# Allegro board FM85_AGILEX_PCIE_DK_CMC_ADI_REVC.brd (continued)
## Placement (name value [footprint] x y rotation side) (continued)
R383  20.0K  [0402]  7.32 34.02 90 top
R384  10.0K  [0402]  40.49 16.97 90 top
R385  22.0  [0402]  34.83 15.01 0 top
R391  10  [0402]  36.32 30.2 45 bottom
R401  DNI  [0402]  25.03 35.26 0 top
R408  1K  [0402]  26.35 50.52 270 bottom
R409  1K  [0402]  26.35 49.74 270 bottom
R412  1K  [0402]  28.1 49.74 270 bottom
R413  10.0K  [0402]  26.37 48.95 90 bottom
R414  DNI  [0402]  244.48 31.07 90 bottom
R415  10.0K  [0402]  244.86 32.51 0 bottom
R416  10.0K  [0402]  244.02 32.51 0 bottom
R423  10.0K  [0402]  27.77 34.37 0 bottom
R429  1K  [0402]  230.51 106 180 bottom
R430  1K  [0402]  229.37 105.97 180 bottom
R431  1K  [0402]  233.05 106 180 bottom
R434  1K  [0402]  225.15 105.97 180 bottom
R435  10.0K  [0402]  54.24 12.52 270 bottom
R436  DNI  [0402]  41.16 61.17 180 bottom
R437  DNI  [0402]  40.14 61.17 180 bottom
R438  0,DNI  [0402]  39.12 61.17 180 bottom
R439  DNI  [0402]  38.11 61.17 180 bottom
R440  33.2  [0402]  51.32 13.16 270 bottom
R441  DNI  [0402]  37.09 61.17 180 bottom
R442  DNI  [0402]  35.06 61.17 180 bottom
R443  33.2  [0402]  51.32 14.3 270 bottom
R444  4.7K  [0402]  42.17 61.17 180 bottom
R445  10.0K  [0402]  49.16 11 180 bottom
R446  33.2  [0402]  47.25 13.92 180 bottom
R447  33.2  [0402]  48.52 13.92 180 bottom
R448  4.7K  [0402]  244.1 50.37 270 bottom
R449  4.7K  [0402]  244.1 51.39 270 bottom
R450  4.7K  [0402]  244.1 52.4 270 bottom
R451  10.0K  [0402]  46.62 11 0 bottom
R452  4.7K  [0402]  244.1 54.43 270 bottom
R453  10.0K  [0402]  74.64 78.34 180 bottom
R454  0  [0402]  68.42 81.77 270 top
R455  0  [0402]  68.42 80.75 270 top
R456  0  [0402]  68.42 79.73 270 top
R457  4.7K  [0402]  251.85 57.23 180 bottom
R458  0  [0402]  68.42 78.72 270 top
R459  0  [0402]  72.69 77.45 180 bottom
R460  0  [0402]  76.17 78.72 90 bottom
R461  0  [0402]  73.58 77.45 180 bottom
R462  10.0K  [0402]  29.47 52.4 180 bottom
R463  10.0K  [0402]  31.5 52.4 180 bottom
R464  10.0K  [0402]  34.55 52.4 180 bottom
R465  10.0K  [0402]  174.02 92.03 270 bottom
R466  10.0K  [0402]  32.27 62.69 0 bottom
R467  10.0K DNI  [0402]  30.49 52.4 0 bottom
R468  10.0K DNI  [0402]  32.52 52.4 0 bottom
R469  10.0K DNI  [0402]  33.54 52.4 0 bottom
R470  0  [0402]  166.02 89.87 90 bottom
R471  0  [0402]  166.02 90.88 90 bottom
R472  0  [0402]  166.02 91.8 90 bottom
R473  0  [0402]  166.05 92.76 90 bottom
R474  DNI  [0402]  169.96 95.46 0 bottom
R475  DNI  [0402]  170.97 95.46 0 bottom
R476  750  [0402]  174.02 91.01 270 bottom
R477  200K  [0402]  245.29 92.15 270 bottom
R478  DNI  [0402]  242.2 79.2 180 bottom
R479  5.49M  [0402]  240.29 73.36 270 bottom
R480  4.7K  [0402]  240.42 79.2 0 bottom
R481  10.0K  [0402]  241.31 79.2 180 bottom
R482  0  [0402]  243.09 79.2 0 bottom
R483  10  [0402]  217.05 85.93 180 top
R484  100K  [0402]  241.18 72.34 90 bottom
R485  100K  [0402]  212.61 86.57 180 bottom
R486  200K  [0402]  242.07 73.36 270 bottom
R487  41.2K  [0402]  217.18 88.6 270 bottom
R488  5.76K  [0402]  217.18 89.49 90 bottom
R489  240  [0402]  217.18 91.26 270 bottom
R490  1K  [0402]  214 85.8 0 bottom
R491  DNI  [0402]  211.21 86.57 90 bottom
R492  5.49M  [0402]  214.76 82.12 0 bottom
R493  4.7K  [0402]  211.93 80.6 270 bottom
R494  10.0K  [0402]  211.59 84.79 180 top
R495  0  [0402]  211.21 87.58 270 bottom
R496  100K  [0402]  214.76 83.9 180 bottom
R497  200K  [0402]  214.89 85.8 0 bottom
R498  10.0K  [0402]  241.94 73.1 0 top
R499  10.0K  [0402]  238.89 73.1 0 top
R500  200K  [0402]  240.67 79.58 0 top
R501  60.4K  [0402]  244.74 79.2 0 bottom
R502  1.91K  [0402]  240.16 78.18 90 top
R503  60.4K  [0402]  243.72 70.06 180 bottom
R504  20.0K  [0402]  243.72 71.96 0 bottom
R505  6.04K  [0402]  239.66 79.58 180 top
R546  0  [0402]  227.97 20.86 180 bottom
R547  0  [0402]  229.11 20.86 180 bottom
R578  100K  [0402]  232.52 59.95 180 bottom
R579  200K  [0402]  232.54 61.76 0 bottom
R580  10  [0402]  233.15 66.12 180 bottom
R581  DNI  [0402]  229.37 59.72 90 bottom
R582  100K  [0402]  231.22 59.95 180 bottom
R583  100K  [0402]  231.91 64.82 90 bottom
R584  DNI  [0402]  229.47 63.86 90 bottom
R585  DNI  [0402]  232.54 63.58 180 bottom
R586  DNI  [0402]  232.93 57.71 270 top
R587  100K  [0402]  229.47 62.59 90 bottom
R588  0  [0402]  231.38 63.41 0 bottom
R589  24.9K  [0402]  231.15 62 270 bottom
R590  8.25K  [0402]  231.16 58.85 90 top
R621  0  [0402]  236.64 20.27 0 top
R622  0  [0402]  239.88 20.26 0 top
R656  10K  [0402]  42.32 102.77 270 bottom
R657  35.7K  [0402]  43.47 105.82 0 top
R658  332K  [0402]  38.39 105.82 180 top
R659  14K  [0402]  43.72 104.04 180 top
R660  10K,DNI  [0402]  37.12 105.18 270 bottom
R661  14K  [0402]  42.7 104.04 180 top
R662  10K  [0402]  36.46 104.14 90 bottom
R663  1.0  [0402]  34.83 102.52 270 top
R664  10K,DNI  [0402]  37.37 105.82 180 top
R665  0  [0402]  95.26 82.25 0 bottom
R666  0  [0402]  96.27 82.25 0 bottom
R667  10K,DNI  [0402]  36.46 105.82 0 top
R668  10K  [0402]  208.44 36.17 0 bottom
R669  35.7K  [0402]  210.7 33.73 270 top
R670  332K  [0402]  209.43 37.16 90 top
R671  10K,DNI  [0402]  209.3 38.05 180 bottom
R672  10K  [0402]  208.41 38.05 0 bottom
R673  1.0  [0402]  206.13 39.45 180 top
R674  14K  [0402]  207.65 30.64 90 top
R675  14K  [0402]  207.63 31.57 90 top
R676  10K,DNI  [0402]  209.43 38.05 90 top
R677  0  [0402]  101.12 36.45 180 bottom
R678  0  [0402]  102.01 36.45 180 bottom
R679  10K,DNI  [0402]  209.43 38.94 270 top
R768  825E  [0402]  177.48 38.67 90 bottom
R815  10.0K  [0402]  47.42 28.63 0 top
R816  10.0K,DNI  [0402]  46.45 27.64 0 top
R817  0  [0402]  48.19 24.59 180 bottom
R818  10.0K  [0402]  46.45 25.38 180 top
R819  10.0K  [0402]  40.66 28.53 180 bottom
R820  10.0K  [0402]  39.76 30.03 90 bottom
R821  10.0K  [0402]  23.79 109.39 90 top
R822  10.0K, DNI  [0402]  25.83 109.54 90 top
R823  0  [0402]  25.83 108.65 270 top
R824  10.0K  [0402]  27.79 109 270 top
R825  10.0K  [0402]  20.75 107.89 180 top
R826  10.0K  [0402]  22.56 107.89 180 top
R835  DNI  [1206]  41.16 83.52 270 bottom
R836  0  [0402]  35.06 84.91 0 bottom
R837  4.7K  [0402]  35.06 82.88 180 bottom
R838  DNI  [0402]  31.5 81.87 90 bottom
R839  0  [0402]  31.5 80.98 90 bottom
R840  4.7K  [0402]  31.5 80.09 270 bottom
R853  0,DNI  [RESC1005X40L20L]  178.58 55.01 180 top
R854  1K  [0402]  244.1 49.35 90 bottom
R856  10.0K  [0402]  105.54 69.7 60 bottom
R857  0  [0402]  14.61 59.64 90 bottom
R858  0  [0402]  44.76 31.98 180 top
R859  0  [0402]  45.55 31.98 180 top
R865  0  [0402]  86.27 74.34 90 bottom
R866  1K  [0402]  105.55 70.7 60 bottom
R867  1K  [0402]  103.98 66.97 240 bottom
R868  36  [0402]  71.04 18.43 90 bottom
R869  36  [0402]  73.34 18.53 270 bottom
R870  36  [0402]  71.04 17.61 90 bottom
R871  36  [0402]  73.34 19.33 270 bottom
R872  36  [0402]  71.04 19.25 90 bottom
R873  36  [0402]  77.72 18.41 90 bottom
R874  36  [0402]  67.49 18.48 270 bottom
R875  36  [0402]  75.62 15.69 0 bottom
R876  36  [0402]  67.49 16 270 bottom
R877  36  [0402]  73.79 15.69 0 bottom
R878  36  [0402]  71.04 20.07 90 bottom
R879  36  [0402]  69.53 15.95 0 bottom
R880  36  [0402]  73.34 20.13 270 bottom
R881  36  [0402]  74.68 15.69 0 bottom
R882  36  [0402]  67.49 21.78 270 bottom
R883  36  [0402]  76.83 22.79 90 bottom
R884  36  [0402]  76.83 23.66 90 bottom
R885  36  [0402]  67.49 20.95 270 bottom
R886  36  [0402]  76.83 21.91 90 bottom
R887  36  [0402]  67.49 19.31 270 bottom
R888  36  [0402]  77.06 21 90 bottom
R889  36  [0402]  73.34 20.93 270 bottom
R890  36  [0402]  71.04 21.73 90 bottom
R891  36  [0402]  71.04 20.9 90 bottom
R892  36  [0402]  165.34 18.36 270 bottom
R893  36  [0402]  168.07 18.37 90 bottom
R894  36  [0402]  165.34 17.54 270 bottom
R895  36  [0402]  168.07 19.19 90 bottom
R896  36  [0402]  165.34 19.19 270 bottom
R897  36  [0402]  172.23 18.34 90 bottom
R898  36  [0402]  162.01 18.41 270 bottom
R899  36  [0402]  170.14 15.62 0 bottom
R900  36  [0402]  163.48 15.22 0 bottom
R901  36  [0402]  167.09 16.26 0 bottom
R902  36  [0402]  165.34 20.01 270 bottom
R903  36  [0402]  164.47 15.83 0 bottom
R904  36  [0402]  168.07 20.01 90 bottom
R905  36  [0402]  169.2 15.62 0 bottom
R906  36  [0402]  162.01 21.71 270 bottom
R907  36  [0402]  171.85 22.8 90 bottom
R908  36  [0402]  171.34 23.59 90 bottom
R909  36  [0402]  162.01 20.88 270 bottom
R910  36  [0402]  171.85 21.92 90 bottom
R911  36  [0402]  162.01 19.24 270 bottom
R912  36  [0402]  172.08 21.02 90 bottom
R913  36  [0402]  168.07 20.84 90 bottom
R914  36  [0402]  165.34 21.67 270 bottom
R915  36  [0402]  165.34 20.84 270 bottom
R916  4.7K  [0402]  65.41 45.93 270 bottom
R917  0  [0402]  66.17 49.35 90 bottom
R918  0,DNI  [0402]  65.41 46.94 90 bottom
R920  100K  [0402]  65.41 48.08 90 bottom
R921  10.0K  [0402]  73.54 46.56 90 bottom
R923  100K  [0402]  73.54 49.86 270 bottom
R925  66.5K  [0402]  73.54 48.85 90 bottom
R926  0  [0402]  175.16 53.73 180 bottom
R927  10.0K  [0402]  140.6 34.49 90 bottom
R928  0  [0402]  63.94 38.38 270 top
R929  0  [0402]  63.94 37.37 270 top
R930  0  [0402]  64.65 40.54 270 top
R931  0  [0402]  64.65 39.53 270 top
R932  0  [0402]  204.86 61.17 270 bottom
R933  0  [0402]  204.86 60.15 270 bottom
R934  0  [0402]  204.83 63.88 270 bottom
R935  0  [0402]  204.83 63.07 270 bottom
R936  49.9  [0402]  100.79 54.21 240 bottom
R937  49.9  [0402]  100.81 51.73 302 bottom
R939  49.9  [0402]  131.87 56.39 60 bottom
R941  49.9  [0402]  131.86 58.8 123 bottom
R942  10K  [0402]  56.4 102.82 270 bottom
R943  20k  [0402]  57.54 105.87 180 top
R944  169K  [0402]  52.46 105.87 180 top
R945  10.0K  [0402]  57.79 104.09 180 top
R946  10K,DNI  [0402]  51.19 105.23 270 bottom
R947  16.5K  [0402]  56.78 104.09 0 top
R948  10K  [0402]  50.43 104.35 90 bottom
R949  1.0  [0402]  48.9 102.57 270 top
R950  10K,DNI  [0402]  51.44 105.87 180 top
R951  0  [0402]  111.06 84.14 0 bottom
R952  0  [0402]  112.07 84.14 0 bottom
R953  10K,DNI  [0402]  50.43 105.87 0 top
R955  100K  [0402]  199.07 53.72 0 bottom
R956  100K  [0402]  199.4 55.02 90 bottom
R957  DNI  [0402]  206.56 56.31 90 top
R958  0  [0402]  203.33 50.14 90 bottom
R959  DNI  [0402]  201.43 49.25 270 bottom
R960  DNI  [0402]  206.58 55.38 270 top
R961  10  [0402]  99.85 36.45 0 bottom
R963  10  [0402]  98.84 36.45 180 bottom
R964  75K  [0402]  201.4 51.42 180 bottom
R965  100K  [0402]  202.9 45.88 90 bottom
R966  100K  [0402]  200.31 46.18 0 top
R967  DNI  [0402]  207.84 48.11 180 top
R969  0  [0402]  205.24 41.61 90 bottom
R970  332K  [0402]  206.53 41.51 180 bottom
R971  DNI  [0402]  203.33 40.72 270 bottom
R972  DNI  [0402]  208.29 46.81 270 top
R973  10  [0402]  127.26 36.65 0 bottom
R975  10  [0402]  126.25 36.65 180 bottom
R976  75K  [0402]  200.39 42.6 90 bottom
R977  4.7K  [0402]  202.9 45.09 90 bottom
R978  332K  [0402]  206.08 49.74 180 bottom
R979  4.7K  [0402]  201 53.47 90 bottom
R980  DNI  [0402]  205.32 54.57 0 bottom
R981  DNI  [0402]  203.7 43.83 45 bottom
R982  0  [0402]  249.82 46.94 270 bottom
R983  1K  [0402]  52.59 35.51 270 top
R984  1K  [0402]  53.47 33.86 0 top
R985  49.9  [0402]  55.51 34.45 270 top
R986  49.9  [0402]  57.28 34.45 90 top
R987  49.9  [0402]  59.19 34.37 270 top
R988  49.9  [0402]  60.97 34.37 90 top
R993  49.9  [0402]  214.97 57.1 270 bottom
R994  DNI  [0402]  204.48 66.14 0 bottom
R995  1K  [0402]  203.46 66.14 0 bottom
R996  49.9  [0402]  213.06 57.1 90 bottom
R997  49.9  [0402]  211.08 57.36 270 bottom
R998  49.9  [0402]  209.18 57.36 90 bottom
R999  4.7K  [0402]  97.72 32.44 270 bottom
R1000  0  [0402]  57.94 12.4 270 bottom
R1001  10.0K, DNI  [0402]  59.93 13.97 270 bottom
R1034  240  [0402]  97.87 36.45 0 bottom
R1047  10.0K  [0402]  144.79 105.44 0 bottom
R1048  DNI  [0402]  147.35 107.37 180 bottom
R1049  10.0K  [0402]  141.8 100.96 90 bottom
R1050  DNI  [0402]  94.18 30.73 0 bottom
R1051  DNI  [0402]  140.58 30.01 180 top
R1052  DNI  [0402]  87.3 53.25 90 bottom
R1062  DNI  [0402]  117.44 40.15 115.5 bottom
R1063  0  [0402]  57.92 30.94 0 top
R1064  0  [0402]  58.94 30.94 0 top
R1065  0  [0402]  53.86 30.94 0 top
R1066  0  [0402]  54.87 30.94 0 top
R1067  DNI  [0402]  120.62 82.79 0 bottom
R1068  10.0K, DNI  [0402]  73.03 97.61 90 bottom
R1069  10.0K, DNI  [0402]  72.12 98.63 90 bottom
R1070  DNI  [0402]  112.6 105.2 0 bottom
R1071  DNI  [0402]  113.28 102.59 180 bottom
R1072  0  [0402]  111.8 105.21 0 bottom
R1073  0  [0402]  112.49 102.6 180 bottom
R1074  DNI  [0402]  112.43 98.82 0 bottom
R1075  0  [0402]  112.88 100.08 90 bottom
R1076  DNI  [0402]  112.55 93.89 0 bottom
R1077  0  [0402]  112.53 95.58 180 bottom
R2206  DNI  [0402]  232.01 93.7 0 bottom
R2635  4K7  [0201]  40.4 26.44 180 top
R2637  4K7 DNI  [0201]  36 27.92 0 bottom
R2653  4K7  [0201]  14.95 18.22 0 top
R2654  4K7  [0201]  16.83 20.21 180 top
R2691  33R2  [0201]  12.33 17.68 90 top
R2692  33R2  [0201]  11.84 19.23 180 top
R2693  33R2  [0201]  14.33 20.75 90 top
R2694  33R2  [0201]  12.76 20.25 0 top
R2695  33R2  [0201]  12.83 21.08 0 top
R2696  33R2  [0201]  10.9 18.24 180 top
R2697  33R2  [0201]  10.9 17.25 180 top
R2698  33R2  [0201]  10.93 16.21 180 top
R2699  10.0K  [0402]  7.26 18.12 180 bottom
R2700  10.0K  [0402]  5.74 22.95 135 bottom
R2707  4.7K  [0402]  137.83 31.02 90 bottom
R2714  4.7K  [0402]  46.03 13.9 0 bottom
R2715  0  [0402]  199.4 21.77 0 top
R2716  0  [0402]  201.05 18.38 270 top
R2717  1K  [0402]  2.29 54.66 270 bottom
R2718  1K  [0402]  2.27 52.83 270 bottom
R2719  1K  [0402]  2.29 49.03 270 bottom
R2721  0  [0402]  14 50.78 0 bottom
R2725  10.0K  [0402]  14.36 49.15 90 bottom
R2726  10.0K  [0402]  14.82 50.75 180 bottom
R2727  10.0K  [0402]  231.99 95.43 180 bottom
R2730  DNI  [0402]  2.27 53.83 90 bottom
R2731  DNI  [0402]  2.27 52 90 bottom
R2732  DNI  [0402]  2.29 49.97 90 bottom
R2734  0  [0402]  232.88 94.41 180 bottom
R2735  0  [0402]  231.12 95.43 0 bottom
R2736  22.0  [0402]  226.11 105.98 0 bottom
R2738  10.0K  [0402]  124.52 36.65 0 bottom
R2739  20k  [0402]  125.41 36.65 180 bottom
R2740  10.0K  [0402]  39.28 18.87 180 bottom
R2741  56.2  [0402]  15.06 107.21 90 bottom
R2742  4K7  [0201]  201.05 19.17 0 top
R2743  4K7  [0201]  201.05 17.49 0 top
R2779  10.0K  [0402]  185.38 92.1 180 bottom
R2780  10.0K, DNI  [0402]  184.44 92.1 180 bottom
R2781  0  [0402]  181.82 91.66 90 bottom
R2782  10.0K  [0402]  183.47 92.1 180 bottom
R2783  10.0K  [0402]  189.57 96.8 0 bottom
R2784  10.0K  [0402]  189.29 95.48 90 bottom
R2785  19.1k  [0402]  205.68 14.5 180 top
R2786  0, DNI  [0402]  204.11 20.79 90 bottom
R2788  10.0K  [0402]  206.23 18.8 270 bottom
R2794  30.1k  [0402]  67.47 37.47 90 bottom
R5835  0  [0402]  192.66 78.31 0 bottom
R5836  0,DNI  [0402]  190.05 77.52 180 bottom
R5837  0  [0402]  192.46 80.72 270 bottom
R5838  0,DNI  [0402]  194.95 80.72 90 bottom
R5839  10.0K  [0402]  188.83 82.43 180 bottom
R5840  10.0K  [0402]  189.82 79.15 315 bottom
R5841  10K,DNI  [0402]  186.27 84.45 0 bottom
R5842  10.0K  [0402]  186.03 81.79 315 bottom
R5845  10.0K, DNI  [0402]  186.55 83.21 90 bottom
R5847  0  [0402]  187.55 84.77 0 bottom
R5848  10.0K  [0402]  188.51 76.61 135 bottom
R5849  0,DNI  [0402]  190.96 83.26 0 bottom
R5850  0  [0402]  187.28 81.77 315 bottom
R5853  1.62K  [RESC1005X40L20L]  188.83 80.74 135 bottom
R5854  0,DNI  [0402]  189.14 79.76 135 bottom
R5870  5.11K  [0402]  181.64 55.01 180 top
R5871  3.09K  [0402]  182.47 55.01 180 top
R5873  6.49K  [0402]  183.3 55.01 180 top
R5875  10k  [0402]  176.11 58.6 0 top
R5876  10k  [0402]  176.18 59.38 0 bottom
R5877  10k  [0402]  176.76 57.24 270 top
R5878  10k  [0402]  185.81 56.21 90 top
R5881  499E  [0402]  176.11 64.9 90 top
R5882  499E  [0402]  183.55 63.81 180 bottom
R5883  499E  [0402]  176.11 64.04 90 top
R5884  1E  [RESC1005X40L20L]  174.49 69.9 180 bottom
R5885  0  [RESC1005X40L20L]  175.41 66.37 0 top
R5886  0  [RESC1005X40L20L]  175.11 74.06 0 top
R5887  100  [RESC1005X40L20L]  176.33 61.52 90 bottom
R5888  100  [RESC1005X40L20L]  176.21 62.33 90 bottom
R5890  0  [RESC1005X40L20L]  175.39 51.89 0 top
R5891  0  [RESC1005X40L20L]  174.89 59.01 270 top
R5893  0  [RESC1005X40L20L]  174.89 38.81 90 top
R5894  0  [RESC1005X40L20L]  175.52 43.97 270 top
R5923  4.22K  [0402]  185.97 80.43 135 bottom
R5924  15.4K  [0402]  185.98 79.14 315 bottom
R5925  0  [0402]  73.31 73.79 90 bottom
R5926  0,DNI  [0402]  73.31 71.9 270 bottom
R5927  0  [0402]  71.97 73.65 0 bottom
R5928  0,DNI  [0402]  69.88 76.13 180 bottom
R5929  10K  [0402]  68.1 70.01 270 bottom
R5930  10K  [0402]  73.87 70.01 270 bottom
R5931  10K  [0402]  70.21 66.2 270 bottom
R5934  10K,DNI  [0402]  69.37 68.46 0 bottom
R5936  10K  [0402]  67.3 67.47 90 bottom
R5937  0  [0402]  67.49 68.76 90 bottom
R5938  10K  [0402]  73.74 68.69 270 bottom
R5939  0,DNI  [0402]  68.12 71.88 90 bottom
R5940  0  [0402]  70.61 67.46 270 bottom
R5941  4.7K  [0402]  70.7 68.74 90 bottom
R5944  5.23K  [0402]  71.94 67.49 180 bottom
R5945  15.4K  [0402]  73.59 67.44 270 bottom
R5946  825E  [0402]  70.67 70.26 180 bottom
R5947  0  [0402]  71.94 70.21 180 bottom
R5948  10.0K  [0402]  177.48 35.96 90 bottom
R5949  1.65K  [0402]  177.48 39.58 270 bottom
R5950  0,DNI  [0402]  177.48 36.87 270 bottom
R5952  0  [0402]  195.21 42.8 0 top
R5953  0  [0402]  196.04 44.64 180 top
R5954  0.005E  [RES_CSNL2512_0_005-0_006]  194.84 42.8 270 bottom
R5955  0  [0402]  195.31 37.23 0 top
R5956  10.0K  [0402]  177.55 43.13 270 bottom
R5957  10.0K  [0402]  176.42 42.68 0 top
R5958  10.0K  [0402]  180.22 36.66 90 bottom
R5959  10.0K  [0402]  177.59 45.72 270 bottom
R6002  0,DNI  [0402]  70.17 87.99 90 bottom
R6003  0,DNI  [0402]  68.04 87.37 270 bottom
R6004  0  [0402]  68.03 88.98 90 bottom
R6005  4.7K  [0402]  68.04 88.19 270 bottom
R6006  30.1k  [0402]  70.11 82.73 270 bottom
R6008  0,DNI  [0402]  15.18 56.57 270 bottom
R6012  60.4K  [0402]  17.46 62.49 180 bottom
R6013  7.5K  [0402]  75.19 60.05 180 bottom
R6024  10k  [0402]  176.93 54.81 0 top
R6025  10k  [0402]  176.97 55.02 180 bottom
R6026  18.7K  [0402]  181.08 57.05 180 bottom
R6035  499E  [0402]  179.56 64.44 0 bottom
R6036  10k  [0402]  176.2 56.8 0 bottom
R6037  10k  [0402]  179.41 55.01 0 top
R6039  0  [RESC1005X40L20L]  174.4 80.98 0 bottom
R6040  0  [RESC1005X40L20L]  174.01 87.55 180 bottom
R6041  100, DNI  [RESC1608X60L27N]  159.24 91.09 180 bottom
R6043  100  [RESC1005X40L20L]  192.56 26.69 270 bottom
R6044  100K  [R0402]  187.04 19.36 90 bottom
R6045  10K  [0402]  184.31 20.46 0 bottom
R6048  6.65K  [0402]  178.25 69.9 270 top
R6049  10.0K  [0402]  177.81 67.59 180 top
R6050  1.2 OHM  [RC0402]  180.4 65.89 0 top
R6051  2.32K  [0402]  184.04 66 90 top
R6053  4.12K  [0402]  200.29 65.84 180 top
R6054  0  [0402]  194.88 81.99 90 bottom
R6056  0  [0402]  70.67 76.11 180 bottom
R6057  4.7K  [0402]  43.01 14.61 270 top
R6058  4.7K  [0402]  44.62 14.07 270 bottom
R6059  4.7K  [0402]  45.6 21.89 270 bottom
R6060  4.7K  [0402]  43.88 21.88 270 bottom
R6061  10K  [0402]  37.85 44.58 0 top
R6065  0,DNI  [0402]  177.81 55.01 180 bottom
R6066  1E  [RESC1005X40L20L]  174.68 84.28 180 bottom
R6067  1E  [RESC1005X40L20L]  174.51 56.03 180 bottom
R6068  1E  [RESC1005X40L20L]  174.95 41.57 180 bottom
R6069  10k  [0402]  196.45 63.35 180 top
R6074  215K  [0402]  199.45 61.14 45 top
R6075  0  [RESC1005X40L20L]  200.26 62.23 180 top
R6076  100K  [0402]  198 62.23 270 top
R6077  100K  [0402]  69.6 31.45 270 bottom
R6078  100K  [0402]  67.78 31.46 270 bottom
R6079  0, DNI  [0402]  184.28 22.53 180 bottom
R6080  0  [0402]  181.54 24.46 90 bottom
R6081  4.7K  [0402]  183.01 24.78 180 bottom
R6082  15K  [0402]  191.29 26.24 180 bottom
R6084  0, DNI  [0402]  209.05 97.57 0 top
R6085  0  [0402]  217.94 96.32 0 top
R6086  4.7K  [0402]  213.41 97.35 180 top
R6087  15K  [0402]  207.51 95.29 180 top
R6088  100  [RESC1005X40L20L]  208.42 95.29 180 top
R6089  100K  [R0402]  212.86 102.26 180 top
R6090  10K  [0402]  209.05 102.26 180 top
R6091  0, DNI  [0402]  65.67 58.83 270 bottom
R6092  0  [0402]  67.55 58.47 180 bottom
R6093  4.7K  [0402]  66.3 60.53 180 bottom
R6095  0  [0402]  75.19 58.37 180 bottom
R6096  100K  [R0402]  70.11 56.75 0 bottom
R6097  10K  [0402]  67.51 56.12 0 bottom
R6098  0,DNI  [0402]  30.33 37.47 0 bottom
R6100  19.1k  [0402]  35.48 37.95 90 bottom
R6101  162K  [RC0402]  17.94 36.91 0 bottom
R6102  4.7K  [0402]  19.64 37.39 180 bottom
R6103  13.3K  [0402]  23.88 39.07 180 bottom
R6104  0,DNI  [0402]  7.2 37.19 0 bottom
R6106  30.1k  [0402]  12.58 38.81 180 bottom
R6107  DNI  [0402]  35.9 50.85 180 bottom
R6108  0  [0402]  16.72 40.36 270 bottom
R6109  100K  [0402]  19.13 39.14 0 bottom
R6110  100K, DNI  [0402]  20.35 39.17 0 bottom
R6111  0  [0402]  17.81 42.5 0 bottom
R6112  0,DNI  [0402]  21.62 38.28 0 bottom
R6115  0  [0402]  29.75 42.57 0 bottom
R6116  0,DNI  [0402]  33.59 38.56 90 bottom
R6117  100K, DNI  [0402]  32.29 39.22 0 bottom
R6118  100K  [0402]  31.02 39.22 0 bottom
R6119  0  [0402]  29.01 40.87 180 bottom
R6121  0  [0402]  27.19 57.23 90 bottom
R6122  0  [0402]  16.87 59.64 270 bottom
R6123  0,DNI  [0402]  16.87 60.54 90 bottom
R6124  100K, DNI  [0402]  16.87 57.93 270 bottom
R6125  100K  [0402]  16.87 56.12 270 bottom
R6127  0  [0402]  6.38 40.85 180 bottom
R6128  0  [0402]  10.09 35.51 270 bottom
R6129  0,DNI  [0402]  10.78 37.21 180 bottom
R6130  100K, DNI  [0402]  9.41 38.64 315 bottom
R6131  100K  [0402]  7.83 38.98 0 bottom
R6132  4.7K  [0402]  31.6 37.47 180 bottom
R6133  4.7K  [0402]  16.87 57.01 90 bottom
R6134  4.7K  [0402]  8.47 37.2 180 bottom
R6136  0  [0402]  73.97 87.35 270 bottom
R6137  0,DNI  [0402]  70.09 86.52 0 bottom
R6138  100K, DNI  [0402]  71.36 86.54 180 bottom
R6139  100K  [0402]  72.63 87.56 0 bottom
R6141  0  [0402]  207.91 21.16 180 bottom
R6142  0, DNI  [0402]  203.59 16.42 180 bottom
R6143  100K, DNI  [0402]  204.55 17.66 270 bottom
R6144  100K  [0402]  206.38 21.39 90 bottom
R6145  100K  [R0402]  62.29 36.17 270 bottom
R6146  10.0K  [0402]  185 82.46 180 bottom
R6147  10K,DNI  [0402]  69.37 70.14 180 bottom
R6148  4.7K  [0402]  187.84 81.03 315 bottom
R6154  20k  [0402]  71.97 71.96 0 bottom
R6156  20k  [0402]  191.2 79.76 180 bottom
R6158  0  [0402]  70.06 72.55 90 bottom
R6159  0  [0402]  190.15 81.99 270 bottom
R6163  10.0K,DNI  [0402]  177.57 43.94 270 bottom
R6164  10.0K  [0402]  181.9 37.82 270 bottom
R6165  4.7K  [0402]  177.55 40.46 90 bottom
R6166  0,DNI  [0402]  65.87 35.87 90 bottom
R6167  0  [0402]  65.03 37.92 270 bottom
R6168  4.7K  [0402]  65.03 36.86 90 bottom
R6169  0  [0402]  183.95 39.12 90 bottom
R6170  22.6K  [0402]  181.95 39.73 180 bottom
R6171  0,DNI  [0402]  202.72 19.95 180 bottom
R6172  0  [0402]  202.72 18.26 180 bottom
R6173  4.7K  [0402]  204.73 19.85 90 bottom
R6174  10.0K  [0402]  29.52 17.5 0 bottom
R6175  10.0K  [0402]  27.41 17.2 90 bottom
R6176  10.0K  [0402]  25.5 17.2 90 bottom
R6183  0  [0402]  224.24 106 0 bottom
R6184  1K  [0402]  227.13 105.95 0 bottom
R6185  10.0K  [0402]  28.76 34.62 0 bottom
R6186  10.0K  [0402]  29.6 34.62 0 bottom
R6187  10.0K  [0402]  30.46 34.62 180 bottom
R6188  DNI  [0402]  31.29 34.61 0 bottom
R6189  10.0K  [0402]  26.1 34.8 180 top
R6190  DNI  [0402]  26.4 34.17 90 bottom
R6191  4.7K  [0402]  127.34 31.73 90 bottom
R6192  4K7 DNI  [0201]  40.09 28.32 270 top
R6193  4K7  [0201]  40.4 27.23 180 top
R6194  0  [0402]  181.86 65.13 90 bottom
R6195  6.49K  [0402]  182.04 57.04 0 bottom
R6196  0  [0402]  180.55 55.01 180 top
R6199  0  [0402]  175.76 46.9 90 top
R6201  0  [0402]  192.62 83.42 180 bottom
R6202  0  [0402]  68.16 73.61 180 bottom
R6209  10.0K  [0402]  21.62 23.37 0 top
R6210  10.0K  [0402]  2.47 35.33 0 bottom
R6211  10.0K  [0402]  1.45 35.33 0 bottom
R6213  20  [0402]  37.47 17.43 180 bottom
R6214  20  [0402]  38.41 18.41 180 bottom
R6215  10.0K  [0402]  27.97 24.9 270 bottom
R6216  10.0K  [0402]  137.34 33.35 0 bottom
R6217  10.0K  [0402]  46.36 19.48 0 top
R6218  10.0K  [0402]  197.16 16.21 0 top
R6219  10.0K  [0402]  17.43 44.2 0 bottom
R6220  10.0K  [0402]  36.51 43.06 0 top
R6221  10.0K  [0402]  9.53 34.24 180 bottom
R6222  10.0K  [0402]  18.63 64.14 270 bottom
R6223  10.0K  [0402]  73.97 86.11 90 bottom
R6224  20  [0402]  36.06 23.89 90 bottom
R6225  20  [0402]  37.01 22.87 90 bottom
R6228  20  [0402]  32.93 33.56 270 bottom
R6229  20  [0402]  25.35 31.46 180 bottom
R6230  20  [0402]  29.97 22.85 270 bottom
R6231  20  [0402]  40.65 23.95 270 top
R6232  20  [0402]  40.65 22.35 270 top
R6233  20  [0402]  40.65 25.56 270 top
R6234  20  [0402]  40.65 21.96 90 bottom
R6235  20  [0402]  40.65 24.75 270 top
R6236  20  [0402]  40.65 21.54 270 top
R6237  20  [0402]  40.65 23.15 270 top
R6238  20  [0402]  40.47 29.48 270 top
R6239  20  [0402]  40.47 32.69 270 top
R6240  20  [0402]  40.47 30.28 270 top
R6241  20  [0402]  32.22 34.83 180 bottom
R6242  20  [0402]  33.01 34.83 0 top
R6243  20  [0402]  33.82 34.83 180 bottom
R6244  20  [0402]  33.81 34.83 0 top
R6245  20  [0402]  34.61 34.83 0 top
R6246  20  [0402]  32.2 34.83 0 top
R6247  20  [0402]  35.41 34.83 0 top
R6248  20  [0402]  35.46 34.83 180 bottom
R6249  20  [0402]  40.47 31.08 270 top
R6253  20  [0402]  40.47 31.89 90 top
R6254  1K  [0402]  40.47 33.49 90 top
R6255  0  [RESC1005X40L20L]  178.34 56.62 90 bottom
R6256  0  [RESC1005X40L20L]  175.34 54.79 0 top
R6257  0  [RESC1005X40L20L]  176.13 54.79 0 top
R6258  0  [RESC1005X40L20L]  176.16 54.99 180 bottom
R6260  0,DNI  [0402]  185.86 67.39 0 top
R6261  10K  [0402]  234.14 38.64 0 top
R6262  49.9K  [0402]  231.07 38.64 0 top
R6263  110K  [0402]  235.16 38.64 0 top
R6264  10.0K  [0402]  229.72 39.53 90 top
R6265  10K,DNI  [0402]  236.71 40.97 0 top
R6266  56.2K  [0402]  229.72 38.67 90 top
R6267  10K  [0402]  237.7 40.97 180 top
R6268  1.0  [0402]  237.04 42.37 90 top
R6269  10K,DNI  [0402]  236.15 38.61 0 top
R6270  0  [0402]  230.34 40.39 270 top
R6271  0  [0402]  229.72 36.96 270 top
R6272  10K,DNI  [0402]  237.09 38.61 180 top
R6273  10k  [0402]  174.7 85.19 180 top
R6274  10k  [0402]  174.91 71.22 180 top
R6275  10k  [0402]  175.32 56.95 180 top
R6276  10k  [0402]  175.87 42.55 0 bottom
R6277  0  [RESC1005X40L20L]  176.07 61.47 270 top
R6278  0  [RESC1005X40L20L]  176.51 62.82 180 top
R6279  0  [RESC1005X40L20L]  177.1 56.8 0 bottom
R6280  10.0K, DNI  [0402]  102.86 82.64 180 bottom
R6283  4.7K,DNI  [0402]  177.55 42.24 90 bottom
R6284  0  [0402]  177.55 41.35 270 bottom
R6285  4.7K  [0402]  137.8 34.13 0 top
R6286  4.7K  [0402]  138.77 34.13 0 top
R6287  0  [0402]  67.24 36.21 0 bottom
R6288  0  [0402]  229.75 41.28 270 top
R6289  4.7K,DNI  [0402]  237.59 20.27 0 top
R6290  4.7K,DNI  [0402]  238.88 20.26 0 top
R6291  0,DNI  [RESC1005X40L20L]  176.28 60.55 270 bottom
R6292  0, DNI  [RESC1005X40L20L]  191.48 62.79 90 top
R6297  0, DNI  [RESC1005X40L20L]  56.28 14.66 270 bottom
R6298  0  [RESC1005X40L20L]  100.02 57.34 65 bottom
R6299  0, DNI  [RESC1005X40L20L]  139.58 30.99 270 bottom
R6302  0  [0402]  199.26 89.35 90 top
R6303  0, DNI  [0402]  132.42 70.4 0 bottom
R6304  0, DNI  [0402]  133.67 70.42 250 bottom
R6305  0  [0402]  199.49 90.16 90 top
R6306  0  [0402]  133.9 67.69 343.3 bottom
R6307  150, DNI  [0402]  132.71 67.01 45 bottom
R6308  0  [0402]  131.21 66.62 135 bottom
R6309  150, DNI  [0402]  132.66 60.56 53.9 bottom
R6310  0  [0402]  134.4 60.46 285.9 bottom
R6311  0  [0402]  131.09 61.44 57.4 bottom
R6312  150, DNI  [0402]  99.95 50.23 123.8 bottom
R6313  0  [0402]  101.27 49.76 180 bottom
R6314  0  [0402]  98.94 48.69 180 bottom
R6316  0  [0402]  205.61 69.72 180 top
R6317  0, DNI  [0402]  206.07 68.14 270 top
R6318  0, DNI  [0402]  206.08 67.35 270 top
R6320  0, DNI  [0402]  59.05 44.02 0 bottom
R6321  0, DNI  [0402]  59.88 44.01 0 bottom
R6322  0  [0402]  60.75 44.92 180 top
R6323  0  [0402]  57.86 44.47 270 top
R6324  10.0K, DNI  [0402]  56.02 13.85 90 bottom
R6325  10.0K, DNI  [0402]  139.61 30.12 270 bottom
S1  PB Switch  [WURTH_6X3P5_TACT_SWITCH]  248.42 66.25 180 top
S2  PB Switch  [WURTH_6X3P5_TACT_SWITCH]  248.42 62.18 180 top
S3  PB Switch  [WURTH_6X3P5_TACT_SWITCH]  248.42 58.12 180 top
S4  PB Switch  [WURTH_6X3P5_TACT_SWITCH]  37.9 38.86 90 top
S5  PB Switch  [WURTH_6X3P5_TACT_SWITCH]  248.42 49.99 180 top
ST1  -  [SHORT]  37.75 37.85 0 bottom
ST2  -  [SHORT]  24.65 39.07 180 bottom
ST3  -  [SHORT]  237.12 36.83 90 top
ST6  -  [SHORT]  190.12 80.81 180 bottom
ST9  -  [SHORT]  45.83 104.3 90 bottom
ST10  -  [SHORT]  208.16 34.24 270 bottom
ST13  -  [SHORT]  176.46 34.63 0 top
ST17  -  [SHORT]  78.54 67.44 180 bottom
ST18  -  [SHORT]  70.73 61.55 0 bottom
ST20  -  [SHORT]  67.47 34.95 90 bottom
ST23  -  [SHORT]  17.25 64.21 270 bottom
ST24  -  [SHORT]  67.11 82.71 270 top
ST25  -  [SHORT]  187.48 26.37 0 bottom
ST26  -  [SHORT]  212.86 95.77 0 top
ST27  -  [SHORT]  204.71 14.05 270 top
ST28  -  [SHORT]  186.06 66.12 90 bottom
ST29  -  [SHORT]  13.47 38.81 180 top
ST30  -  [SHORT]  52.93 107.09 180 bottom
ST31  -  [SHORT]  199.04 56.02 270 bottom
ST32  -  [SHORT]  200.27 40.92 0 bottom
ST34  -  [SHORT]  176.02 46.1 90 top
SW1  TDA04H0SB1  [DIPSWITCH_SMT_QUAD]  177.12 21.52 180 bottom
SW2  TDA04H0SB1  [DIPSWITCH_SMT_QUAD]  8.52 84.66 90 bottom
SW3  TDA04H0SB1  [DIPSWITCH_SMT_QUAD]  8.52 77.35 90 bottom
SW4  TDA04H0SB1  [DIPSWITCH_SMT_QUAD]  8.52 59.9 270 bottom
SW5  TDA04H0SB1  [DIPSWITCH_SMT_QUAD]  8.52 52.58 270 bottom
SW6  SW_SLIDE_DPDT  [EG2207]  248.79 76.25 270 top
SW8  TDA04H0SB1  [DIPSWITCH_SMT_QUAD]  19.89 51.87 270 bottom
TP1  TESTPOINT  [30MIL_TP]  21.52 34.5 0 top
TP8  TESTPOINT  [30MIL_TP]  225.65 65.32 0 top
TP9  TESTPOINT  [30MIL_TP]  225.65 62.16 0 top
TP14  TESTPOINT  [30MIL_TP]  34.82 104.74 270 top
TP15  TESTPOINT  [30MIL_TP]  212.25 41.66 0 top
TP18  TESTPOINT  [30MIL_TP]  47.89 105.87 270 top
TP19  TEST PAD  [PADSTYLE1]  200.59 57.51 0 top
TP20  TEST PAD  [PADSTYLE1]  203.81 51.86 180 bottom
TP21  TEST PAD  [PADSTYLE1]  211.84 43.77 0 top
TP22  TEST PAD  [PADSTYLE1]  199.4 47.2 0 top
TP24  TESTPOINT  [30MIL_TP]  2.74 55.66 180 bottom
TP25  TESTPOINT  [30MIL_TP]  2.68 50.91 180 bottom
TP27  TESTPOINT  [30MIL_TP]  14.11 53.22 180 bottom
TP28  TESTPOINT  [30MIL_TP]  14.51 43.67 0 top
TP29  TESTPOINT  [30MIL_TP]  73.31 70.94 180 bottom
TP950  TESTPOINT  [30MIL_TP]  40.29 18.19 0 top
TP951  TESTPOINT  [30MIL_TP]  123.38 36.98 180 bottom
TP954  TESTPOINT  [30MIL_TP]  232.44 92.02 0 top
TP955  TESTPOINT  [30MIL_TP]  229.74 94.04 0 top
TP956  TESTPOINT  [30MIL_TP]  222.16 90.12 0 top
TP957  TESTPOINT  [30MIL_TP]  219.64 85.93 0 top
TP958  TESTPOINT  [30MIL_TP]  231.07 82.12 0 top
TP959  TESTPOINT  [30MIL_TP]  232.75 87.07 0 top
TP960  TESTPOINT  [30MIL_TP]  207.59 69.13 0 top
TP961  TESTPOINT  [30MIL_TP]  209.5 69.13 0 top
TP962  TESTPOINT  [30MIL_TP]  213.7 71.21 0 top
TP963  TESTPOINT  [30MIL_TP]  217.94 70.9 0 top
TP964  TESTPOINT  [30MIL_TP]  211.13 76.8 0 top
TP965  TESTPOINT  [30MIL_TP]  211.21 82.71 0 top
TP966  TESTPOINT  [30MIL_TP]  155.63 89.23 0 top
TP967  TESTPOINT  [30MIL_TP]  154.95 59.39 0 top
TP968  TESTPOINT  [30MIL_TP]  234.42 66.42 0 top
TP969  TESTPOINT  [30MIL_TP]  24.72 42.95 180 top
TP970  TESTPOINT  [30MIL_TP]  27.13 35.54 180 top
TP971  TESTPOINT  [30MIL_TP]  233.89 56.37 0 top
TP972  TESTPOINT  [30MIL_TP]  181.32 88.52 0 top
TP973  TESTPOINT  [30MIL_TP]  197.16 51.95 0 top
TP974  TESTPOINT  [30MIL_TP]  199.91 43.77 0 top
TP975  TESTPOINT  [30MIL_TP]  41.94 93.25 0 top
TP976  TESTPOINT  [30MIL_TP]  195.87 28.78 0 top
TP977  TESTPOINT  [30MIL_TP]  175.93 50.47 0 top
TP979  TESTPOINT  [30MIL_TP]  55.96 93.25 0 top
TP980  TESTPOINT  [30MIL_TP]  80.6 64.76 0 top
TP981  TESTPOINT  [30MIL_TP]  63.51 49.94 0 top
TP982  TESTPOINT  [30MIL_TP]  68.88 34.69 180 bottom
TP983  TESTPOINT  [30MIL_TP]  13.46 42.78 180 top
TP984  TESTPOINT  [30MIL_TP]  29.27 62.28 0 bottom
TP985  TESTPOINT  [30MIL_TP]  72.64 44.66 0 top
TP986  TESTPOINT  [30MIL_TP]  81.92 91.26 90 top
TP987  TESTPOINT  [30MIL_TP]  184.94 17.48 180 bottom
TP988  TESTPOINT  [30MIL_TP]  205.63 102.53 90 top
TP989  TESTPOINT  [30MIL_TP]  66.86 14 0 top
TP990  TESTPOINT  [30MIL_TP]  119.64 15.6 0 top
TP991  TESTPOINT  [30MIL_TP]  27.69 103.71 90 top
TP992  TESTPOINT  [30MIL_TP]  27.98 107.89 90 top
TP994  TESTPOINT  [30MIL_TP]  33.41 80.29 180 bottom
TP995  TESTPOINT  [30MIL_TP]  176.74 68.25 0 top
TP996  TESTPOINT  [30MIL_TP]  193.89 68.53 0 top
TP997  TESTPOINT  [30MIL_TP]  187.15 67.85 0 top
TP998  TESTPOINT  [30MIL_TP]  131.24 96.34 180 bottom
TP999  TESTPOINT  [30MIL_TP]  186.7 89.44 180 bottom
TP1000  TESTPOINT  [30MIL_TP]  192.44 71.21 0 top
TP1001  TESTPOINT  [30MIL_TP]  175.82 35.69 0 top
TP1002  TESTPOINT  [30MIL_TP]  176.16 37.56 0 top
TP1004  TESTPOINT  [30MIL_TP]  202.64 60.56 0 top
TP1005  TESTPOINT  [30MIL_TP]  236.13 34.31 0 top
TP1006  TESTPOINT  [30MIL_TP]  187.15 71 0 top
TP1007  TESTPOINT  [30MIL_TP]  75.57 68.7 180 bottom
TP1008  TESTPOINT  [30MIL_TP]  207.82 14.78 0 top
U1  MT40A1G16KNR-075:E  [FBGA96]  92.54 22.94 0 top
U2  MT40A1G16KNR-075:E  [FBGA96]  112.86 22.94 0 top
U3  MT40A1G16KNR-075:E  [FBGA96]  82.38 22.94 0 top
U4  MT40A1G16KNR-075:E  [FBGA96]  102.7 22.94 0 top
U5  MT40A1G16KNR-075:E  [FBGA96]  72.19 22.93 0 top
U6  AgileX-I_2957A  [FBGA2957A_HEX_P56X45]  116.21 59.39 180 top
U7  MT40A1G16KNR-075:E  [FBGA96]  126.07 22.86 0 top
U8  MT40A1G16KNR-075:E  [FBGA96]  136.23 22.86 0 top
U9  MT40A1G16KNR-075:E  [FBGA96]  146.39 22.86 0 top
U10  MT40A1G16KNR-075:E  [FBGA96]  156.55 22.9 0 top
U11  MT40A1G16KNR-075:E  [FBGA96]  166.71 22.86 0 top
U12  MAX3378E  [TSSOP-14]  92.31 100.41 90 bottom
U13  MAX3378E  [TSSOP-14]  100.44 100.28 90 bottom
U14  FPC202RHUR  [QFN-56]  22.36 84.15 90 bottom
U15  MAX3378E  [TSSOP-14]  102.64 32.5 0 bottom
U16  24AA024-I/SN  [SOIC-8]  51.82 17.86 0 bottom
U17  SN74AUP1G08DCKR  [DCK]  57.54 13.79 90 top
U18  MAX3378E  [TSSOP-14]  202.65 90.81 0 bottom
U19  SN74AUP1G126DCK  [SC70_TI]  141.03 32.59 270 bottom
U21  REF1112AIDBZR  [SOT23-3]  100.79 86.27 180 bottom
U22  Si5391A-A12892-GM  [QFN64_9X9_SI5391]  54.49 24.08 90 top
U23  Si52204-A01BGM  [QFN32L]  47.89 38.56 0 top
U24  Si53254A-D02AM  [SI53254_QFN40]  58.17 39.65 90 top
U25  Si53254A-D02AM  [SI53254_QFN40]  210.59 63.35 90 bottom
U26  FXMA2102UMX  [UMLP]  18.47 108.72 0 bottom
U27  FXMA2102UMX  [UMLP]  18.51 104.22 0 bottom
U28  MAX3378E  [TSSOP-14]  28.58 97.11 270 top
U29  MAX3378E  [TSSOP-14]  60.51 32.79 180 bottom
U30  MAX3378E  [TSSOP-14]  44.2 27.13 90 bottom
U31  MAX3378E  [TSSOP-14]  21.72 97.11 270 top
U32  MAX3378E  [TSSOP-14]  14.87 97.11 270 top
U33  MAX811  [SOT-143]  39.45 35.51 180 bottom
U34  10M50DAF256C7G  [256FBGA]  31 25.4 0 top
U35  TPD2EUSB30  [DRT]  5.75 28.63 90 top
U36  MT25QU02GCBB8E12-0SIT  [T-PBGA24]  3.73 19.07 0 top
U38  TS3A5018RSVR  [UQFN-16]  17.93 17.57 90 top
U39  SN74LVC2G17DCKR  [SC70-6]  53.17 13.81 180 top
U40  TXS0108EPWR  [20-TSSOP]  39.12 55.83 0 bottom
U41  SN74LVC2G17DCKR  [SC70-6]  47.9 12.07 90 top
U42  TXS0108EPWR  [20-TSSOP]  248.93 51.89 0 bottom
U43  M24128-BWMN6TP  [SO8]  31.63 57.61 90 bottom
U44  FDMC2514SDC  [FDMC8878_VER2]  229.75 90.38 180 top
U45  FDMC2514SDC  [FDMC8878_VER2]  229.75 84.53 90 top
U46  LTC4357  [DFN6_EPAD]  225.05 91.77 90 top
U47  LTC4365-1  [DFN8-EPAD_3X2]  241.31 76.02 180 bottom
U48  LTC4359  [MSOP-8]  214.38 86.18 180 top
U49  FDMC2514SDC  [FDMC8878_VER2]  213.11 73.87 270 top
U50  FDMC2514SDC  [FDMC8878_VER2]  213.11 80.09 270 top
U51  LTC4357  [DFN6_EPAD]  212.73 71.71 90 bottom
U52  LTC4365-1  [DFN8-EPAD_3X2]  212.48 83.9 270 bottom
U53  TPS3700  [DDC]  240.42 75.9 90 top
U66  LTM4657EY  [LTC-BGA-49-1518]  202.19 53.42 90 top
U67  LTM4657EY  [LTC-BGA-49-1518]  204.1 45.04 90 top
U68  LTC7151SEV  [LQFN_28_5MMX4MM]  39.02 101.25 0 top
U69  LTC7151SEV  [LQFN_28_5MMX4MM]  204.86 35.26 270 top
U71  LTC7151SEV  [LQFN_28_5MMX4MM]  53.09 101.3 0 top
U84  TPS51200DRCR  [VSON-11]  43.84 27.13 270 top
U85  TPS51200DRCR  [VSON-11]  25.7 105.7 0 top
U87  FDMC2514SDC  [FDMC8878_VER2]  37.73 83.77 180 bottom
U88  LTC4365-1  [DFN8-EPAD_3X2]  32.77 84.03 0 bottom
U103  W956D8MBYA6I  [TFBGA24]  13.85 18.71 90 bottom
U104  MT25QU02GCBB8E12-0SIT  [T-PBGA24]  3.73 18.07 180 bottom
U105  TXS0108EPWR  [20-TSSOP]  132.64 33.94 270 bottom
U106  TXS0108EPWR  [20-TSSOP]  43.84 18.04 270 bottom
U107  TCA9539RTWR  [QFN50P410X410X80-25-CUST]  197.94 19.42 180 bottom
U108  TPS51200DRCR  [VSON-11]  188.22 91.8 270 bottom
U114  LTM4643EY#PBF  [BGA77C127P7X11_900X1500X262N]  70.73 56.96 90 top
U116  LTM4622EV#PBF  [LGA25C127P5X5_625X625X192N]  197.72 61.6 0 bottom
U117  LTM4668IY#PBF  [BGA49C80P7X7_625X625X230N]  71.28 37.06 0 top
U118  LTM4686EV-1#PBF  [LGA108C127P9X12_1190X1600X192N]  189.46 80.74 0 top
U119  LTC3888IUHG-1#PBF  [QFN40P500X800X80-53N]  181.09 60.54 0 top
U120  LTC7051AV#PBF  [ANALOG_LQFN-42P]  170.98 84.2 0 top
U121  LTC7051AV#PBF  [ANALOG_LQFN-42P]  171.1 70.16 0 top
U122  LTM4625  [BGA25]  233.15 62.59 90 top
U123  LTM4623EY#PBF  [BGA25C127P5X5_625X625X262]  19.72 40.36 180 top
U124  LTM4623EY#PBF  [BGA25C127P5X5_625X625X262]  31.6 40.46 180 top
U125  LTC7051AV#PBF  [ANALOG_LQFN-42P]  171.02 56.16 0 top
U126  LTC7051AV#PBF  [ANALOG_LQFN-42P]  170.94 41.35 0 top
U128  LTM4623EY#PBF  [BGA25C127P5X5_625X625X262]  22.05 59.64 270 bottom
U129  MAX15053EWL+T  [BGA9N50P3X3_149X149X69N]  183.14 67.82 90 top
U130  ADP1752ACPZ-1.0-R7  [QFN65P400X400X80-17NA]  190.48 68.03 90 top
U131  ADP1752ACPZ-1.0-R7  [QFN65P400X400X80-17NA]  197.24 68 90 top
U132  LT3042IDD#PBF  [LT3042IDD]  69.86 47.32 90 bottom
U133  LTM4623EY#PBF  [BGA25C127P5X5_625X625X262]  71.99 86.73 90 top
U134  LTM4623EY#PBF  [BGA25C127P5X5_625X625X262]  205.98 19.48 90 top
U135  LTM4678EY#PBF  [BGA144C127P12X12_1600X1600X626]  185.76 40.39 180 top
U136  LTM4686EV-1#PBF  [LGA108C127P9X12_1190X1600X192N]  70.67 70.63 90 top
U137  LTC7151SEV  [LQFN_28_5MMX4MM]  233.43 43.23 180 top
U138  LTM4643EY#PBF  [BGA77C127P7X11_900X1500X262N]  187.48 21.29 90 top
U139  LTM4643EY#PBF  [BGA77C127P7X11_900X1500X262N]  212.86 100.57 270 bottom
U141  TCA9517ADGKR  [VSSOP-8]  43.98 18.21 0 top
U142  LTM4623EY#PBF  [BGA25C127P5X5_625X625X262]  8.47 40.19 180 top
U143  CY7C68013A_QFN  [QFN56]  14.36 29.11 90 top
Y1  48MHz  [XTAL_3MMX2MM]  54.24 16.6 180 top
Y2  25.00MHz  [XTAL_FA-128]  41.54 39.32 90 top
Y3  24.00MHz  [XTAL_FA-128]  9.56 21.92 180 top
Y4  100MHz  [XTAL_KC2520Z]  37.07 15.29 180 top

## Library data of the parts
B1 B2 = Molex_QSFPDD_Cage
C1-C4 C6 C7 C9-C25 C28-C50 C52 C53 C55-C71 C74-C95 C99-C102 C104 C105 C107-C123 C126-C148 C150 C151 C153-C169 C172-C192 C194 C197-C199 C201 C211 C213 C215 C220 C221 C226 C229 C237 C241 C243 C245 C247 C249 C256 C260 C263 C265 C267 C271 C275 C280 C282 C286 C290 C295-C305 C308-C310 C319 C321 C323-C325 C327 C329-C331 C333 C335 C340 C353 C392 C393 C395 C396 C417-C422 C434 C438 C471 C477-C482 C491 C498 C561 C562 C567 C570 C715 C716 C824 C826 C977 C983 C985 C986 C997 C998 C1024 C1026 C1027 C1029 C1030 C1032 C1033 C1038 C1039 C1046-C1048 C1050 C1053 C1057-C1060 C1064 C1065 C1067-C1070 C1094-C1100 C1105-C1107 C1111 C1112 C1114 C1121-C1123 C1127-C1131 C1133 C1134 C1164 C1167 C1190 C1195 C1200 C1205 C1223 C1240 C1242 C1246-C1251 C1266 C1271 C1286 C1315 C1323 C1327 C1329-C1332 C1340 C1341 C1366-C1369 C1371 C1385 C1389-C1391 C1395 C1398 C1400-C1402 C1404-C1420 C1422 C1427 C1456 C1714 C1720 C1721 C1960 C1966 C1967 C2004 C7403 C7433 C7435 C7436 C7439 C7461-C7464 C7522 C7608 C7614 C7615 C7618 C7624 C7625 C7627 C7631 C7637 C7650 C7654 C7656 C7660 C7663 C7665 C7671 C7683 C7692 C7704 C7707 C7711 C7714 C7725-C7759 C7761 C7764-C7766 C7773 C7774 C7777 C7778 = CAP: Tolerance: TOL; User Part Number: PART#
C5 C8 C26 C27 C51 C54 C72 C73 C96 C97 C103 C106 C124 C125 C149 C152 C170 C171 C193 C195 C212 C217 C246 C252 C266 C268-C270 C272-C274 C276-C279 C281 C283-C285 C287-C289 C291-C294 C394 C407-C415 C618 C783-C785 C823 C978-C982 C984 C987-C996 C1062 C1090-C1092 C1101-C1104 C1116-C1118 C1120 C1132 C1154 C1155 C1176 C1177 C1180 C1183 C1265 C1317 C1318 C1320 C1342 C1343 C1351 C1354 C1355 C1372 C1375 C1376 C1381 C1382 C1386 C1387 C1438 C1439 C1443 C1444 C1446 C1715 C1716 C1719 C1887-C1889 C1893 C1894 C1964 C7466-C7470 C7472-C7475 C7479-C7481 C7585-C7587 C7589 C7592 C7597 C7598 C7610-C7612 C7620-C7622 C7661 C7775 C7776 = CAP: User Part Number: *; Tolerance: *
C98 C196 = CAP: Tolerance: TOL; User Part Number: PART#; signal model: RESISTOR_0402_36_36
C200 C202 C210 C222 C224 C230 C238 C242 C244 C251 C259 C264 C7563 = Cap 10000PF 50V 0402: Tolerance: TOL; User Part Number: PART#
C203 C205 C207 C209 C214 C223 C231-C233 C235 C239 C248 C250 C257 C370-C372 C389-C391 C423-C433 C435-C437 C439-C444 C455-C464 C472 C483-C490 C492 C493 C495-C497 C499 C501 C503-C510 C512 C514-C522 C524-C540 C542-C546 C548 C549 C551-C560 C565 C572 C573 C579 C581 C587 C589 C597 C720 C726 C804 C807-C809 C815 C816 C821 C825 C833 C835 C892 C1019-C1023 C1025 C1028 C1031 C1037 C1040 C1044 C1045 C1049 C1051 C1052 C1054-C1056 C1063 C1066 C1108-C1110 C1115 C1161 C1186-C1188 C1191-C1193 C1196-C1198 C1201-C1203 C1208-C1210 C1212-C1215 C1217-C1220 C1222 C1224 C1225 C1227 C1239 C1241 C1243 C1284 C1293 C1294 C1309-C1314 C1316 C1321 C1322 C1324 C1345-C1348 C1350 C1364 C1392-C1394 C1396 C1397 C1399 C1403 C1421 C1423-C1426 C1428-C1430 C2028 C7397-C7402 C7404 C7406 C7422 C7434 C7437 C7438 C7518 C7525 C7526 C7569 C7574 C7575 C7602 C7604 C7655 C7669 C7670 C7672 C7676 C7681 C7682 C7686 C7689-C7691 C7697 C7698 C7700 C7702 C7703 C7706 C7718 C7779 = CAP: User Part Number: PART#; Tolerance: TOL
C204 C206 C208 C225 C234 C236 C240 C258 C7560 = Cap 10000PF 50V 0402: User Part Number: PART#; Tolerance: TOL
C216 C227 C253 C261 C404-C406 C494 C500 C502 C523 C541 C547 C550 C582 C806 C817-C820 C832 C834 C837 C838 C891 C1061 C1093 C1113 C1119 C1124-C1126 C1152 C1153 C1178 C1179 C1181 C1182 C1184 C1185 C1277 C1319 C1325 C1326 C1338 C1339 C1360 C1361 C1431 C1445 C1891 C1892 C1962 C1963 C7405 C7423-C7432 C7590 C7591 C7593-C7595 C7599 = CAP: Tolerance: *; User Part Number: *
C218 C219 C228 C254 C255 C262 = CAP 10uF +/-10% 25V 1210: Tolerance: *; User Part Number: *
C306 C307 C311-C318 C320 C322 C326 C328 C332 C334 C336-C339 C341-C352 = CAP: signal model: CAP_0402_0.22UF_0.22uF
C354-C369 C373-C388 = CAP: signal model: CAP_SMC0201IA_0.22UF_0.22uF
C397 C416 C1034-C1036 C1041-C1043 C1135-C1151 C1159 C1160 C1162 C1163 C1165 C1166 C1168-C1175 C1189 C1194 C1199 C1204 C1211 C1216 C1221 C1226 C1232-C1238 C1244 C1245 C1255-C1262 C1267-C1270 C1272 C1273 C1279 C1280 C1283 C1447-C1449 = CAP
C445-C448 = CAP: Tolerance: TOL; User Part Number: PART#; signal model: RESISTOR_0402_10K_10K
C451-C454 = CAP: User Part Number: PART#; Tolerance: TOL; signal model: RESISTOR_0402_10K_10K
C465-C467 C473 C474 C1451 C1452 = CAP: User Part Number: PART#; Tolerance: TOL; signal model: CAP_0402_0.1UF_0.1uF
C468 C475 C476 = CAP: Tolerance: TOL; User Part Number: PART#; signal model: CAP_0402_0.1UF_0.1uF
C513 C574 C580 C583-C586 C588 C590-C596 C814 C831 C1004 C1886 C7465 C7477 C7478 C7584 C7596 C7600 C7771 C7772 = PCAP
C563 C568 C569 C571 C727 C1388 C1533 C1582 C1728 C1729 C1731 C1741 C1742 C7580-C7583 C7717 C7720 C7780 C7781 = Cap, NP, 0402: Tolerance: TOL; User Part Number: PART#
C564 C566 C725 C1356 C1564 C1565 C1718 C1730 C7556 C7558 C7559 C7561 C7562 C7566-C7568 C7578 C7579 C7664 C7678 C7715 C7716 C7721-C7723 C7760 = Cap, NP, 0402: User Part Number: PART#; Tolerance: TOL
C575-C578 C717-C719 C721-C724 C811 C813 C830 C1630-C1633 C1734 C1735 C7517 C7523 C7524 C7564 C7565 C7603 C7605 C7632 C7634 C7638 C7639 C7641 C7647 C7653 C7666 C7684 C7685 C7708 C7713 C7719 = Cap, NP, 1206: Tolerance: *; User Part Number: *
C805 C7642 C7643 = CAP NP: Tolerance: *; User Part Number: *
C810 C812 C827 = Cap, NP, 1206: User Part Number: PART#; Tolerance: TOL
C822 C1328 C7644 C7645 C7651 C7652 = CAP NP: User Part Number: *; Tolerance: *
C828 C1334 C1336 C1560-C1563 C1578-C1581 C1732 C1733 C1743-C1746 C1958 C1959 C7442 C7471 C7519-C7521 C7571 C7572 C7606 C7607 C7616 C7617 C7626 C7630 C7636 C7640 C7646 C7648 C7649 C7667 C7668 C7674 C7699 C7701 C7709 C7712 C7768 C7770 = Cap, NP, 1206: User Part Number: *; Tolerance: *
C829 C1333 C1335 C7767 C7769 = Cap, NP, 1206: Tolerance: TOL; User Part Number: PART#
C1005 = PCAP: Tolerance: *; User Part Number: *
C1006 = CAP_NP: Tolerance: TOL; User Part Number: PART#
C1432 C1433 C1435-C1437 C1440 C1441 = PCAP: User Part Number: PART#; Tolerance: TOL
C1442 = PCAP: Tolerance: TOL; User Part Number: PART#
C1450 C1558 C1559 C1576 C1577 C1750 C1751 C7679 C7680 C7687 C7688 C7693-C7696 = Cap, NP, 0805: User Part Number: PART#; Tolerance: TOL
C1557 C1575 C1622-C1629 C1738 C1749 C7557 = CAPPOL
C1739 C1740 = Cap, NP, 0805: Tolerance: TOL; User Part Number: PART#
C1890 C7588 = T523H227M025APE070
C1961 C7609 C7619 = CAP: Tolerance: *; User Part Number: 150-3503
C7192 C7395 C7396 = CAP: Tolerance: TOL; User Part Number: ECC000114; alternate symbols: (0402CIR_M)
C7394 = CAP: Tolerance: TOL; User Part Number: ECC000170; alternate symbols: (0402CIR_M)
C7783 = TCN4227M025R0100
CN1-CN6 = CAP_ARRAY
D1 D3 D5 D7-D11 D14 = LED_WURTH: User Part Number: *; Tolerance: *
D2 D4 = APHB1608CGKSYKC
D6 = LED_0: User Part Number: *; Tolerance: *
D12 D13 = TVS_5p0SMDJ12A
D17 D18 = PMEG2005AEL,315
EU1 EU2 = MAX31730ATC
FB1 FB6 FB8 FB29 = BEAD_FERRITE_SM: Tolerance: TOL; User Part Number: PART#
FB5 FB7 FB9 FB10 FB13 FB40 L11-L14 = BEAD_FERRITE_SM: User Part Number: PART#; Tolerance: TOL
FB16 FB30 FB32 FB33 FB41 = BEAD_FERRITE_SM: Tolerance: *; User Part Number: *
FB26 = INDUCTOR
FB31 = BEAD_FERRITE_SM: User Part Number: *; Tolerance: *
HW1 = LIGHTPIPE_P-U90-1101-T00A-BP_2
J1 = DDR4x72x288_1
J2 = DDR4x72x288_1: signal model: DDR4X72X288_1_DDR4DIMM_SMT_DDR4X72X288_DDR4x72x288
J3 J4 = 2027180100
J5 = PCIE_Bracket_X16_1
J6 J7 = CON_MCIO_74P_G42V12312HR
J8 = MICRO_USB_CONN
J9 = FAN_Conn_0
J10 = 70247-1051
J11 = 2X4_PCIE_ATX_1: User Part Number: PART#; Tolerance: TOL
J12-J15 = 1x3_HDR_TH
L1-L6 L26 = INDUCTOR IRON
L20-L22 = Inductor, Discrete
L23 L27-L29 = FP0805R1-R07-R
L30 = XGL5030-351MEC
MTH1 MTH2 MTH4 MTH5 = MNT HOLE_1
Q1-Q3 Q5 Q6 = PWRMOSFET_EN_GSD_0: User Part Number: *; Tolerance: *
Q4 Q7-Q12 Q15 = PWRMOSFET_EN_GSD_0: Tolerance: *; User Part Number: *
Q13 = PSMN1R0-30YLD_0
Q14 = PWRMOSFET_EN_GSD_1: User Part Number: *; Tolerance: *
R1-R4 R7-R10 R13-R25 R28 R31 R39-R42 R45-R48 R51-R63 R69 R82 R100 R121-R125 R128-R131 R134-R137 R140 R145 R147 R148 R154-R169 R173 R174 R182 R184 R187 R188 R190 R191 R194 R198-R209 R213-R217 R267 R281-R288 R303-R325 R337 R338 R342 R343 R354 R355 R358 R360 R362 R365 R367 R414-R416 R448-R450 R452 R454-R456 R458 R465 R466 R470-R476 R583-R585 R588 R669 R674 R675 R815-R826 R836-R838 R840 R854 R857 R865 R873 R905 R909 R920 R936 R939 R941 R942 R944 R946-R953 R956 R957 R960 R965-R967 R969-R973 R975 R977 R980-R982 R988 R994 R995 R997-R999 R1047-R1049 R1051 R1068 R1069 R2715-R2717 R2780-R2782 R2785 R2786 R2788 R5835-R5842 R5845 R5847-R5850 R5854 R5870 R5871 R5873 R5881 R5883 R5925-R5931 R5934 R5936-R5941 R5947 R5948 R5950 R6008 R6012 R6013 R6026 R6035 R6043 R6054 R6056 R6076 R6079-R6081 R6084-R6086 R6091-R6093 R6095 R6097 R6098 R6102 R6104 R6106 R6109-R6112 R6115-R6118 R6122-R6125 R6128-R6134 R6136-R6139 R6141-R6144 R6146-R6148 R6158 R6159 R6165 R6171-R6173 R6195 R6201 R6202 R6218 R6222 R6223 R6229 R6261 R6263 R6265-R6272 R6287-R6290 R6302-R6314 R6316 R6320-R6325 = RESISTOR: Tolerance: TOL; User Part Number: PART#
R27 R29 R30 R32 R34-R36 R65-R68 R70 R72-R74 R868-R872 R874-R904 R906-R908 R910-R915 = RESISTOR: Tolerance: TOL; User Part Number: PART#; signal model: RESISTOR_0402_36_36
R33 R71 R79 R84-R86 R97 R101 R102 R152 R546 R547 R621 R622 R839 R917 R926 R1075 R1077 R2730 R5952 R5953 R5955 R6065 R6108 R6119 R6121 R6127 R6194 R6196 = RES 0 OHM 5% 1/16W 0402 SMD: Tolerance: TOL; User Part Number: PART#
R37 R75 R80 R81 R83 R98 R99 R108 R126 R127 R132 R133 R138 R139 R141-R144 R146 R150 R170-R172 R175-R179 R183 R189 R195-R197 R210 R218 R219 R241-R248 R251 R253 R257 R258 R260 R261 R263 R264 R268-R272 R291-R294 R326-R333 R335 R336 R339-R341 R344-R353 R366 R368-R372 R374-R377 R381-R385 R401 R408 R409 R412 R413 R423 R429-R431 R434 R444 R453 R457 R459-R464 R467-R469 R478-R481 R483-R485 R487-R494 R496 R498-R505 R578 R580-R582 R586 R587 R589 R590 R656-R668 R670-R673 R676-R679 R856 R858 R859 R866 R867 R916 R918 R921 R923 R925 R927 R937 R955 R958 R959 R961 R963 R978 R979 R983-R987 R993 R996 R1000 R1001 R1034 R1050 R1052 R1062 R1067 R2699 R2700 R2707 R2714 R2718 R2719 R2721 R2725-R2727 R2734 R2735 R2738 R2740 R2779 R2783 R2784 R2794 R5882 R5956-R5959 R6002-R6006 R6045 R6048 R6049 R6057-R6061 R6077 R6078 R6082 R6087 R6088 R6090 R6100 R6103 R6107 R6163 R6164 R6166-R6170 R6183-R6191 R6209-R6211 R6214 R6215 R6219-R6221 R6228 R6230-R6249 R6253 R6254 R6260 R6280 R6283 R6285 R6286 = RESISTOR: User Part Number: PART#; Tolerance: TOL
R77 R78 R95 R96 = RESISTOR: Tolerance: *; User Part Number: *
R87 R91 = RESISTOR: Tolerance: TOL; User Part Number: PART#; signal model: RESISTOR_0402_10.0K_10.0K
R88-R90 R103 R104 = RESISTOR: Tolerance: TOL; User Part Number: PART#; signal model: RESISTOR_0402_DNI_DNI
R94 R107 R835 = RESISTOR: User Part Number: *; Tolerance: *
R149 R153 = RESISTOR: User Part Number: PART#; Tolerance: TOL; signal model: RESISTOR_0402_4.7K_4.7K
R151 R239 R373 R482 R495 R1063-R1066 R1072 R2731 R2732 R5949 R6199 R6284 = RES 0 OHM 5% 1/16W 0402 SMD: User Part Number: PART#; Tolerance: TOL
R185 R186 = RESISTOR: Tolerance: TOL; User Part Number: PART#; signal model: CAP_SMC0201IA_0.22UF_0.22uF
R211 R212 R435 R445 R451 = RESISTOR: User Part Number: PART#; Tolerance: TOL; signal model: RESISTOR_0402_10.0K_10.0K
R220 R221 R249 R250 R252 R254-R256 R259 R262 R928-R931 R934 R935 R1073 = RES 0 OHM 5% 1/16W 0402 SMD: User Part Number: PART#; Tolerance: TOL; signal model: RES_0_OHM_5%_1/16W_0402_SMD_0402_0_0
R223 R225 = RESISTOR: Tolerance: TOL; User Part Number: PART#; signal model: RESISTOR_0402_0402_33_33
R224 R226 = RESISTOR: User Part Number: PART#; Tolerance: TOL; signal model: RESISTOR_0402_0402_33_33
R227 R228 = RESISTOR: User Part Number: PART#; Tolerance: TOL; signal model: RESISTOR_0402_10K_10K
R229-R232 = RES 0 OHM 5% 1/16W 0402 SMD: Tolerance: TOL; User Part Number: PART#; signal model: RESISTOR_0402_10K_10K
